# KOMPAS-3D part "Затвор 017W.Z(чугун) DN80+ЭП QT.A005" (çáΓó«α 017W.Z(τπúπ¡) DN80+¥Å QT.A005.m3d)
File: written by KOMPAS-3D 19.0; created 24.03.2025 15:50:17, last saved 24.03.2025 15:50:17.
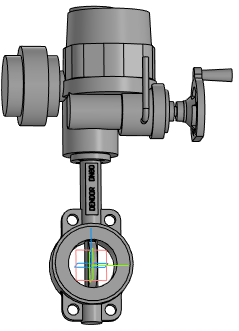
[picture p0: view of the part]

Document properties: Полное имя файла: Затвор 017W.Z(чугун) DN80+ЭП QT.A005.a3d

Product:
- Part/product: Затвор 017W.Z(чугун) DN80+ЭП QT.A005
    Масса: 41.0556

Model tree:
1. Операция без истории:1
